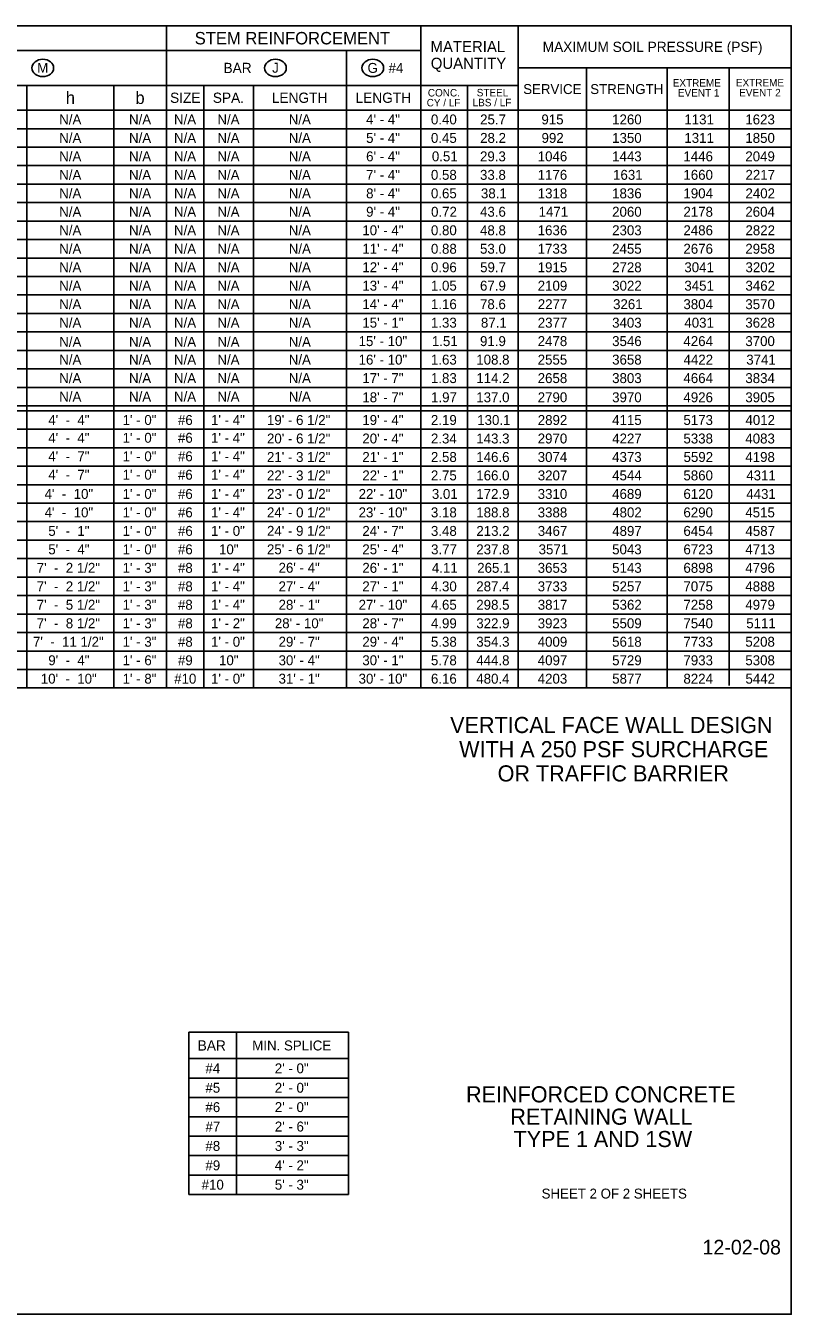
# Model space of a CAD drawing. Extents: x 99862 to 103151, y 100000 to 105076.
# Drawn here: x 101917 to 103151, y 103000 to 105076 of the extents above; entities that cross this region are included whole.
import ezdxf

# ---------------------------------------------------------------- set-up
doc = ezdxf.new("R2010")
doc.units = 0
for name, color, linetype in [('Level 1', 7, 'Continuous'), ('Level 20', 7, 'Continuous'), ('Level 21', 7, 'Continuous'), ('Level 4', 7, 'Continuous'), ('Level 60', 7, 'Continuous'), ('Level 62', 7, 'Continuous'), ('Level 63', 7, 'Continuous')]:
    doc.layers.add(name, color=color, linetype=linetype)

msp = doc.modelspace()

# ---------------------------------------------------------------- linework, layer by layer
at = {"layer": 'Level 1'}
msp.add_lwpolyline([(99862, 102999.5), (103151, 102999.5), (103151, 105075.5), (99862, 105075.5)], close=True, dxfattribs=at)
at = {"layer": 'Level 20'}
for centre in [(101944.5, 105007.5), (102319.5, 105007.5), (102476.4, 105007.5)]:
    msp.add_ellipse(centre, major_axis=(-17.5, 0), ratio=0.8, dxfattribs=at)
at = {"layer": 'Level 4'}
for p, q in [((102144, 104008.6), (102144, 105075.5)), ((102554, 104008.6), (102554, 105075.5)), ((102711, 104008.6), (102711, 105075.5)), ((100414, 105035.5), (102554, 105035.5)), ((102434, 104008.6), (102434, 105035.5)), ((102711, 105007.5), (103151, 105007.5)), ((102821, 104008.6), (102821, 105007.5)), ((102951, 104008.6), (102951, 105007.5)), ((100014, 104979.5), (102711, 104979.5)), ((101919, 104008.6), (101919, 104979.5)), ((102059, 104008.6), (102059, 104979.5)), ((102204, 104008.6), (102204, 104979.5)), ((102284, 104008.6), (102284, 104979.5)), ((102629, 104008.6), (102629, 104979.5)), ((99939, 104939.5), (103151, 104939.5)), ((103151, 104909.7), (99939, 104909.7)), ((103151, 104880), (99939, 104880)), ((103151, 104850.2), (99939, 104850.2)), ((103151, 104820.4), (99939, 104820.4)), ((103151, 104790.6), (99939, 104790.6)), ((103151, 104760.9), (99939, 104760.9)), ((103151, 104731.1), (99939, 104731.1)), ((103151, 104701.3), (99939, 104701.3)), ((103151, 104671.6), (99939, 104671.6)), ((103151, 104641.8), (99939, 104641.8)), ((103151, 104612), (99939, 104612)), ((103151, 104582.2), (99939, 104582.2)), ((103151, 104552.5), (99939, 104552.5)), ((103151, 104522.7), (99939, 104522.7)), ((103151, 104492.9), (99939, 104492.9)), ((103151, 104463.2), (99939, 104463.2)), ((103151, 104455.2), (99939, 104455.2)), ((103151, 104425.4), (99939, 104425.4)), ((103151, 104395.6), (99939, 104395.6)), ((103151, 104365.8), (99939, 104365.8)), ((103151, 104336.1), (99939, 104336.1)), ((103151, 104306.3), (99939, 104306.3)), ((103151, 104276.5), (99939, 104276.5)), ((103151, 104246.8), (99939, 104246.8)), ((103151, 104217), (99939, 104217)), ((103151, 104187.2), (99939, 104187.2)), ((103151, 104157.4), (99939, 104157.4)), ((103151, 104127.7), (99939, 104127.7)), ((103151, 104097.9), (99939, 104097.9)), ((103151, 104068.1), (99939, 104068.1)), ((103151, 104038.4), (99939, 104038.4)), ((102180, 103453.7), (102437.1, 103453.7)), ((102180, 103453.7), (102180, 103192.6)), ((102256.6, 103453.7), (102256.6, 103192.6)), ((102437.1, 103453.7), (102437.1, 103192.6)), ((102180, 103411.3), (102437.1, 103411.3)), ((102180, 103380.1), (102437.1, 103380.1)), ((102180, 103348.8), (102437.1, 103348.8)), ((102180, 103317.6), (102437.1, 103317.6)), ((102180, 103286.3), (102437.1, 103286.3)), ((102180, 103255.1), (102437.1, 103255.1)), ((102180, 103223.8), (102437.1, 103223.8)), ((102180, 103192.6), (102437.1, 103192.6))]:
    msp.add_line(p, q, dxfattribs=at)
for points in [[(99939, 105075.5), (103151, 105075.5)], [(103151, 104008.6), (99939, 104008.6), (99939, 105075.5)], [(103151, 105075.5), (103151, 104008.6)], [(103051, 105007.5), (103051, 104012.6)]]:
    msp.add_lwpolyline(points, dxfattribs=at)
at = {"layer": 'Level 60'}
msp.add_line((103151, 105075.5), (103151, 105075.5), dxfattribs=at)

# ---------------------------------------------------------------- texts
at = {"layer": 'Level 1'}
msp.add_text('12-02-08', height=23.62, dxfattribs=at).set_placement((103008, 103095.8))
at = {"layer": 'Level 20'}
for s, height, p in [('STEM REINFORCEMENT', 20, (102189.4, 105045.5)), ('MATERIAL', 18, (102569.5, 105033)), ('MAXIMUM SOIL PRESSURE (PSF)', 16.5, (102750.3, 105033.3)), ('M', 16, (101935.5, 104999.7)), ('BAR', 16.5, (102235.8, 104999.3)), ('J', 16, (102314.2, 104999.8)), ('G', 16, (102468, 104999.6)), ('#4', 16, (102501.9, 104999.5)), ('QUANTITY', 18, (102569.9, 105006)), ('EXTREME ', 12, (102960, 104977.5)), ('EXTREME', 12, (103061.8, 104977.8)), ('h', 20, (101981.6, 104949.5)), ('b', 20, (102093.8, 104949.5)), ('SIZE', 16.5, (102149.7, 104951.3)), ('SPA.', 16.5, (102218.6, 104951.3)), ('LENGTH', 16.5, (102313.7, 104951.3)), ('LENGTH', 16.5, (102448.7, 104951.3)), ('CONC.', 12, (102565.2, 104961.6)), ('STEEL', 12, (102644, 104961.8)), ('SERVICE', 16, (102718.9, 104965.5)), ('STRENGTH', 16, (102827, 104965.5)), ('EVENT 1', 12, (102968.3, 104961.5)), ('EVENT 2', 12, (103067.1, 104961.8)), ('CY / LF', 12, (102563.3, 104945.6)), ('LBS / LF', 12, (102637.4, 104945.8)), ('915', 16, (102748.3, 104916.6)), ('1260', 16, (102862.3, 104916.6)), ('1131', 16, (102978.7, 104916.6)), ('1623', 16, (103077, 104916.6)), ('992', 16, (102748.5, 104886.8)), ('1350', 16, (102862.3, 104886.8)), ('1311', 16, (102978.7, 104886.8)), ('1850', 16, (103077, 104886.8)), ('1046', 16, (102742.3, 104857.1)), ('1443', 16, (102862.3, 104857.1)), ('1446', 16, (102977.2, 104857.1)), ('2049', 16, (103077, 104857.1)), ('1176', 16, (102742.3, 104827.3)), ('1631', 16, (102863.8, 104827.3)), ('1660', 16, (102977.2, 104827.3)), ('2217', 16, (103077.2, 104827.3)), ('1318', 16, (102742.3, 104797.5)), ('1836', 16, (102862.3, 104797.5)), ('1904', 16, (102977.2, 104797.5)), ('2402', 16, (103077.2, 104797.5)), ('1471', 16, (102743.8, 104767.8)), ('2060', 16, (102862.3, 104767.8)), ('2178', 16, (102977.2, 104767.8)), ('2604', 16, (103077, 104767.8)), ('1636', 16, (102742.3, 104738)), ('2303', 16, (102862.3, 104738)), ('2486', 16, (102977.2, 104738)), ('2822', 16, (103077.2, 104738)), ('1733', 16, (102742.3, 104708.2)), ('2455', 16, (102862.3, 104708.2)), ('2676', 16, (102977.2, 104708.2)), ('2958', 16, (103077, 104708.2)), ('1915', 16, (102742.3, 104678.4)), ('2728', 16, (102862.3, 104678.4)), ('3041', 16, (102978.7, 104678.4)), ('3202', 16, (103077.2, 104678.4)), ('2109', 16, (102742.3, 104648.7)), ('3022', 16, (102862.4, 104648.7)), ('3451', 16, (102978.7, 104648.7)), ('3462', 16, (103077.2, 104648.7)), ('2277', 16, (102742.4, 104618.9)), ('3261', 16, (102863.8, 104618.9)), ('3804', 16, (102977.2, 104618.9)), ('3570', 16, (103077, 104618.9)), ('2377', 16, (102742.4, 104589.1)), ('3403', 16, (102862.3, 104589.1)), ('4031', 16, (102978.7, 104589.1)), ('3628', 16, (103077, 104589.1)), ('2478', 16, (102742.3, 104559.4)), ('3546', 16, (102862.3, 104559.4)), ('4264', 16, (102977.2, 104559.4)), ('3700', 16, (103077, 104559.4)), ('2555', 16, (102742.3, 104529.6)), ('3658', 16, (102862.3, 104529.6)), ('4422', 16, (102977.4, 104529.6)), ('3741', 16, (103078.5, 104529.6)), ('2658', 16, (102742.3, 104499.8)), ('3803', 16, (102862.3, 104499.8)), ('4664', 16, (102977.2, 104499.8)), ('3834', 16, (103077, 104499.8)), ('2790', 16, (102742.3, 104468.9)), ('3970', 16, (102862.3, 104468.9)), ('4926', 16, (102977.2, 104468.9)), ('3905', 16, (103077, 104468.9)), ('2892', 16, (102742.4, 104432.3)), ('4115', 16, (102862.3, 104432.3)), ('5173', 16, (102977.2, 104432.3)), ('4012', 16, (103077.2, 104432.3)), ('2970', 16, (102742.3, 104402.5)), ('4227', 16, (102862.4, 104402.5)), ('5338', 16, (102977.2, 104402.5)), ('4083', 16, (103077, 104402.5)), ('3074', 16, (102742.3, 104372.7)), ('4373', 16, (102862.3, 104372.7)), ('5592', 16, (102977.4, 104372.7)), ('4198', 16, (103077, 104372.7)), ('3207', 16, (102742.4, 104343)), ('4544', 16, (102862.3, 104343)), ('5860', 16, (102977.2, 104343)), ('4311', 16, (103078.5, 104343)), ('3310', 16, (102742.3, 104313.2)), ('4689', 16, (102862.3, 104313.2)), ('6120', 16, (102977.2, 104313.2)), ('4431', 16, (103078.5, 104313.2)), ('3388', 16, (102742.3, 104283.4)), ('4802', 16, (102862.4, 104283.4)), ('6290', 16, (102977.2, 104283.4)), ('4515', 16, (103077, 104283.4)), ('3467', 16, (102742.4, 104253.6)), ('4897', 16, (102862.4, 104253.6)), ('6454', 16, (102977.2, 104253.6)), ('4587', 16, (103077.2, 104253.6)), ('3571', 16, (102743.8, 104223.9)), ('5043', 16, (102862.3, 104223.9)), ('6723', 16, (102977.2, 104223.9)), ('4713', 16, (103077, 104223.9)), ('3653', 16, (102742.3, 104194.1)), ('5143', 16, (102862.3, 104194.1)), ('6898', 16, (102977.2, 104194.1)), ('4796', 16, (103077, 104194.1)), ('3733', 16, (102742.3, 104164.3)), ('5257', 16, (102862.4, 104164.3)), ('7075', 16, (102977.2, 104164.3)), ('4888', 16, (103077, 104164.3)), ('3817', 16, (102742.4, 104134.6)), ('5362', 16, (102862.4, 104134.6)), ('7258', 16, (102977.2, 104134.6)), ('4979', 16, (103077, 104134.6)), ('3923', 16, (102742.3, 104104.8)), ('5509', 16, (102862.3, 104104.8)), ('7540', 16, (102977.2, 104104.8)), ('5111', 16, (103078.5, 104104.8)), ('4009', 16, (102742.3, 104075)), ('5618', 16, (102862.3, 104075)), ('7733', 16, (102977.2, 104075)), ('5208', 16, (103077, 104075)), ('4097', 16, (102742.4, 104045.2)), ('5729', 16, (102862.3, 104045.2)), ('7933', 16, (102977.2, 104045.2)), ('5308', 16, (103077, 104045.2)), ('4203', 16, (102742.3, 104015.5)), ('5877', 16, (102862.4, 104015.5)), ('8224', 16, (102977.2, 104015.5)), ('5442', 16, (103077.2, 104015.5))]:
    msp.add_text(s, height=height, dxfattribs=at).set_placement(p)
for s, p in [('N/A', (101971, 104916.6)), ('N/A', (102083.5, 104916.6)), ('N/A', (102156, 104916.6)), ('N/A', (102226, 104916.6)), ('N/A', (102341, 104916.6)), ('N/A', (101971, 104886.8)), ('N/A', (102083.5, 104886.8)), ('N/A', (102156, 104886.8)), ('N/A', (102226, 104886.8)), ('N/A', (102341, 104886.8)), ('N/A', (101971, 104857.1)), ('N/A', (102083.5, 104857.1)), ('N/A', (102156, 104857.1)), ('N/A', (102226, 104857.1)), ('N/A', (102341, 104857.1)), ('N/A', (101971, 104827.3)), ('N/A', (102083.5, 104827.3)), ('N/A', (102156, 104827.3)), ('N/A', (102226, 104827.3)), ('N/A', (102341, 104827.3)), ('N/A', (101971, 104797.5)), ('N/A', (102083.5, 104797.5)), ('N/A', (102156, 104797.5)), ('N/A', (102226, 104797.5)), ('N/A', (102341, 104797.5)), ('N/A', (101971, 104767.8)), ('N/A', (102083.5, 104767.8)), ('N/A', (102156, 104767.8)), ('N/A', (102226, 104767.8)), ('N/A', (102341, 104767.8)), ('N/A', (101971, 104738)), ('N/A', (102083.5, 104738)), ('N/A', (102156, 104738)), ('N/A', (102226, 104738)), ('N/A', (102341, 104738)), ('N/A', (101971, 104708.2)), ('N/A', (102083.5, 104708.2)), ('N/A', (102156, 104708.2)), ('N/A', (102226, 104708.2)), ('N/A', (102341, 104708.2)), ('N/A', (101971, 104678.4)), ('N/A', (102083.5, 104678.4)), ('N/A', (102156, 104678.4)), ('N/A', (102226, 104678.4)), ('N/A', (102341, 104678.4)), ('N/A', (101971, 104648.7)), ('N/A', (102083.5, 104648.7)), ('N/A', (102156, 104648.7)), ('N/A', (102226, 104648.7)), ('N/A', (102341, 104648.7)), ('N/A', (101971, 104618.9)), ('N/A', (102083.5, 104618.9)), ('N/A', (102156, 104618.9)), ('N/A', (102226, 104618.9)), ('N/A', (102341, 104618.9)), ('N/A', (101971, 104589.1)), ('N/A', (102083.5, 104589.1)), ('N/A', (102156, 104589.1)), ('N/A', (102226, 104589.1)), ('N/A', (102341, 104589.1)), ('N/A', (101971, 104558.3)), ('N/A', (102083.5, 104558.3)), ('N/A', (102156, 104558.3)), ('N/A', (102226, 104558.3)), ('N/A', (102341, 104558.3)), ('N/A', (101971, 104529.6)), ('N/A', (102083.5, 104529.6)), ('N/A', (102156, 104529.6)), ('N/A', (102226, 104529.6)), ('N/A', (102341, 104529.6)), ('N/A', (101971, 104499.8)), ('N/A', (102083.5, 104499.8)), ('N/A', (102156, 104499.8)), ('N/A', (102226, 104499.8)), ('N/A', (102341, 104499.8)), ('N/A', (101971, 104470)), ('N/A', (102083.5, 104470)), ('N/A', (102156, 104470)), ('N/A', (102226, 104470)), ('N/A', (102341, 104470)), ('4\'  -  4"', (101953.4, 104432.3)), ('1\' - 0"', (102073.2, 104432.3)), ('#6', (102162.4, 104432.3)), ('1\' - 4"', (102215.7, 104432.3)), ('4\'  -  4"', (101953.4, 104403.6)), ('1\' - 0"', (102073.2, 104403.6)), ('#6', (102162.4, 104403.6)), ('1\' - 4"', (102215.7, 104403.6)), ('4\'  -  7"', (101953.4, 104373.8)), ('1\' - 0"', (102073.2, 104373.8)), ('#6', (102162.4, 104373.8)), ('1\' - 4"', (102215.7, 104373.8)), ('4\'  -  7"', (101953.4, 104344.1)), ('1\' - 0"', (102073.2, 104344.1)), ('#6', (102162.4, 104344.1)), ('1\' - 4"', (102215.7, 104344.1)), ('4\'  -  10"', (101947.4, 104313.2)), ('1\' - 0"', (102073.2, 104313.2)), ('#6', (102162.4, 104313.2)), ('1\' - 4"', (102215.7, 104313.2)), ('4\'  -  10"', (101947.4, 104283.4)), ('1\' - 0"', (102073.2, 104283.4)), ('#6', (102162.4, 104283.4)), ('1\' - 4"', (102215.7, 104283.4)), ('5\'  -  1"', (101953.4, 104253.6)), ('1\' - 0"', (102073.2, 104253.6)), ('#6', (102162.4, 104253.6)), ('1\' - 0"', (102215.7, 104253.6)), ('5\'  -  4"', (101953.4, 104223.9)), ('1\' - 0"', (102073.2, 104223.9)), ('#6', (102162.4, 104223.9)), ('10"', (102228.6, 104223.9)), ('7\'  -  2 1/2"', (101934.7, 104194.1)), ('1\' - 3"', (102073.2, 104194.1)), ('#8', (102162.4, 104194.1)), ('1\' - 4"', (102215.7, 104194.1)), ('7\'  -  2 1/2"', (101934.7, 104164.3)), ('1\' - 3"', (102073.2, 104164.3)), ('#8', (102162.4, 104164.3)), ('1\' - 4"', (102215.7, 104164.3)), ('7\'  -  5 1/2"', (101934.7, 104134.6)), ('1\' - 3"', (102073.2, 104134.6)), ('#8', (102162.4, 104134.6)), ('1\' - 4"', (102215.7, 104134.6)), ('7\'  -  8 1/2"', (101934.7, 104104.8)), ('1\' - 3"', (102073.2, 104104.8)), ('#8', (102162.4, 104104.8)), ('1\' - 2"', (102215.7, 104104.8)), ('7\'  -  11 1/2"', (101928.7, 104075)), ('1\' - 3"', (102073.2, 104075)), ('#8', (102162.4, 104075)), ('1\' - 0"', (102215.7, 104075)), ('9\'  -  4"', (101953.4, 104045.2)), ('1\' - 6"', (102073.2, 104045.2)), ('#9', (102162.4, 104045.2)), ('10"', (102228.6, 104045.2)), ('10\'  -  10"', (101941.3, 104015.5)), ('1\' - 8"', (102073.2, 104015.5)), ('#10', (102156.3, 104015.5)), ('1\' - 0"', (102215.7, 104015.5))]:
    msp.add_text(s, height=16, rotation=360, dxfattribs=at).set_placement(p)
at = {"layer": 'Level 21'}
for s, p in [('VERTICAL FACE WALL DESIGN', (102601.2, 103935.9)), ('WITH A 250 PSF SURCHARGE', (102615.7, 103896.9)), ('OR TRAFFIC BARRIER', (102677.7, 103857.9))]:
    msp.add_text(s, height=26, rotation=360, dxfattribs=at).set_placement(p)
at = {"layer": 'Level 4'}
for s, height, p in [('4\' - 4"', 16, (102465.7, 104916.6)), ('0.40', 16, (102570.2, 104916.6)), ('25.7', 16, (102649.5, 104916.6)), ('5\' - 4"', 16, (102465.7, 104886.8)), ('0.45', 16, (102570.2, 104886.8)), ('28.2', 16, (102649.5, 104886.8)), ('6\' - 4"', 16, (102465.7, 104857.1)), ('0.51', 16, (102571.7, 104857.1)), ('29.3', 16, (102649.3, 104857.1)), ('7\' - 4"', 16, (102465.7, 104827.3)), ('0.58', 16, (102570.2, 104827.3)), ('33.8', 16, (102649.3, 104827.3)), ('8\' - 4"', 16, (102465.7, 104797.5)), ('0.65', 16, (102570.2, 104797.5)), ('38.1', 16, (102650.8, 104797.5)), ('9\' - 4"', 16, (102465.7, 104767.8)), ('0.72', 16, (102570.4, 104767.8)), ('43.6', 16, (102649.3, 104767.8)), ('10\' - 4"', 16, (102459.6, 104738)), ('0.80', 16, (102570.2, 104738)), ('48.8', 16, (102649.3, 104738)), ('11\' - 4"', 16, (102459.6, 104708.2)), ('0.88', 16, (102570.2, 104708.2)), ('53.0', 16, (102649.3, 104708.2)), ('12\' - 4"', 16, (102459.6, 104678.4)), ('0.96', 16, (102570.2, 104678.4)), ('59.7', 16, (102649.5, 104678.4)), ('13\' - 4"', 16, (102459.6, 104648.7)), ('1.05', 16, (102570.2, 104648.7)), ('67.9', 16, (102649.3, 104648.7)), ('14\' - 4"', 16, (102459.6, 104618.9)), ('1.16', 16, (102570.2, 104618.9)), ('78.6', 16, (102649.3, 104618.9)), ('15\' - 1"', 16, (102459.6, 104589.1)), ('1.33', 16, (102570.2, 104589.1)), ('87.1', 16, (102650.8, 104589.1)), ('15\' - 10"', 16, (102453.6, 104559.4)), ('1.51', 16, (102571.7, 104559.4)), ('91.9', 16, (102649.3, 104559.4)), ('16\' - 10"', 16, (102453.6, 104529.6)), ('1.63', 16, (102570.2, 104529.6)), ('108.8', 16, (102643.3, 104529.6)), ('17\' - 7"', 16, (102459.6, 104499.8)), ('1.83', 16, (102570.2, 104499.8)), ('114.2', 16, (102643.4, 104499.8)), ('18\' - 7"', 16, (102459.6, 104468.9)), ('1.97', 16, (102570.4, 104468.9)), ('137.0', 16, (102643.3, 104468.9)), ('19\' - 4"', 16, (102459.6, 104432.3)), ('2.19', 16, (102570.2, 104432.3)), ('130.1', 16, (102644.8, 104432.3)), ('20\' - 4"', 16, (102459.6, 104402.5)), ('2.34', 16, (102570.2, 104402.5)), ('143.3', 16, (102643.3, 104402.5)), ('21\' - 1"', 16, (102459.6, 104372.7)), ('2.58', 16, (102570.2, 104372.7)), ('146.6', 16, (102643.3, 104372.7)), ('22\' - 1"', 16, (102459.6, 104343)), ('2.75', 16, (102570.2, 104343)), ('166.0', 16, (102643.3, 104343)), ('22\' - 10"', 16, (102453.6, 104313.2)), ('3.01', 16, (102571.7, 104313.2)), ('172.9', 16, (102643.3, 104313.2)), ('23\' - 10"', 16, (102453.6, 104283.4)), ('3.18', 16, (102570.2, 104283.4)), ('188.8', 16, (102643.3, 104283.4)), ('24\' - 7"', 16, (102459.6, 104253.6)), ('3.48', 16, (102570.2, 104253.6)), ('213.2', 16, (102643.4, 104253.6)), ('25\' - 4"', 16, (102459.6, 104223.9)), ('3.77', 16, (102570.4, 104223.9)), ('237.8', 16, (102643.3, 104223.9)), ('26\' - 1"', 16, (102459.6, 104194.1)), ('4.11', 16, (102571.7, 104194.1)), ('265.1', 16, (102644.8, 104194.1)), ('27\' - 1"', 16, (102459.6, 104164.3)), ('4.30', 16, (102570.2, 104164.3)), ('287.4', 16, (102643.3, 104164.3)), ('27\' - 10"', 16, (102453.6, 104134.6)), ('4.65', 16, (102570.2, 104134.6)), ('298.5', 16, (102643.3, 104134.6)), ('28\' - 7"', 16, (102459.6, 104104.8)), ('4.99', 16, (102570.2, 104104.8)), ('322.9', 16, (102643.3, 104104.8)), ('29\' - 4"', 16, (102459.6, 104075)), ('5.38', 16, (102570.2, 104075)), ('354.3', 16, (102643.3, 104075)), ('30\' - 1"', 16, (102459.6, 104045.2)), ('5.78', 16, (102570.2, 104045.2)), ('444.8', 16, (102643.3, 104045.2)), ('30\' - 10"', 16, (102453.6, 104015.5)), ('6.16', 16, (102570.2, 104015.5)), ('480.4', 16, (102643.3, 104015.5)), ('BAR', 16.5, (102194.2, 103424.3)), ('MIN. SPLICE', 16, (102282.2, 103424.5)), ('#4', 16, (102206.7, 103387.7)), ('2\' - 0"', 16, (102318.5, 103387.7)), ('#5', 16, (102206.7, 103356.4)), ('2\' - 0"', 16, (102318.5, 103356.4)), ('#6', 16, (102206.7, 103325.2)), ('2\' - 0"', 16, (102318.5, 103325.2)), ('#7', 16, (102206.8, 103293.9)), ('2\' - 6"', 16, (102318.5, 103293.9)), ('#8', 16, (102206.7, 103262.7)), ('3\' - 3"', 16, (102318.5, 103262.7)), ('#9', 16, (102206.7, 103231.4)), ('4\' - 2"', 16, (102318.5, 103231.4)), ('#10', 16, (102200.6, 103200.2)), ('5\' - 3"', 16, (102318.5, 103200.2))]:
    msp.add_text(s, height=height, dxfattribs=at).set_placement(p)
for s, p in [('19\' - 6 1/2"', (102305.9, 104432.3)), ('20\' - 6 1/2"', (102305.9, 104402.5)), ('21\' - 3 1/2"', (102305.9, 104372.7)), ('22\' - 3 1/2"', (102305.9, 104343)), ('23\' - 0 1/2"', (102305.9, 104313.2)), ('24\' - 0 1/2"', (102305.9, 104283.4)), ('24\' - 9 1/2"', (102305.9, 104253.7)), ('25\' - 6 1/2"', (102305.9, 104223.9)), ('26\' - 4"', (102324.6, 104194.2)), ('27\' - 4"', (102324.6, 104164.3)), ('28\' - 1"', (102324.6, 104134.6)), ('28\' - 10"', (102318.6, 104104.8)), ('29\' - 7"', (102324.6, 104075)), ('30\' - 4"', (102324.6, 104045.2)), ('31\' - 1"', (102324.6, 104015.5))]:
    msp.add_text(s, height=16, rotation=360, dxfattribs=at).set_placement(p)
at = {"layer": 'Level 62'}
msp.add_text('SHEET 2 OF 2 SHEETS', height=16, dxfattribs=at).set_placement((102748.6, 103185.9))
at = {"layer": 'Level 63'}
for s, p in [('REINFORCED CONCRETE', (102626.8, 103340.8)), ('RETAINING WALL', (102698.1, 103304.8)), ('TYPE 1 AND 1SW', (102703.4, 103268.8))]:
    msp.add_text(s, height=26, dxfattribs=at).set_placement(p)

doc.saveas('drawing.dxf')
